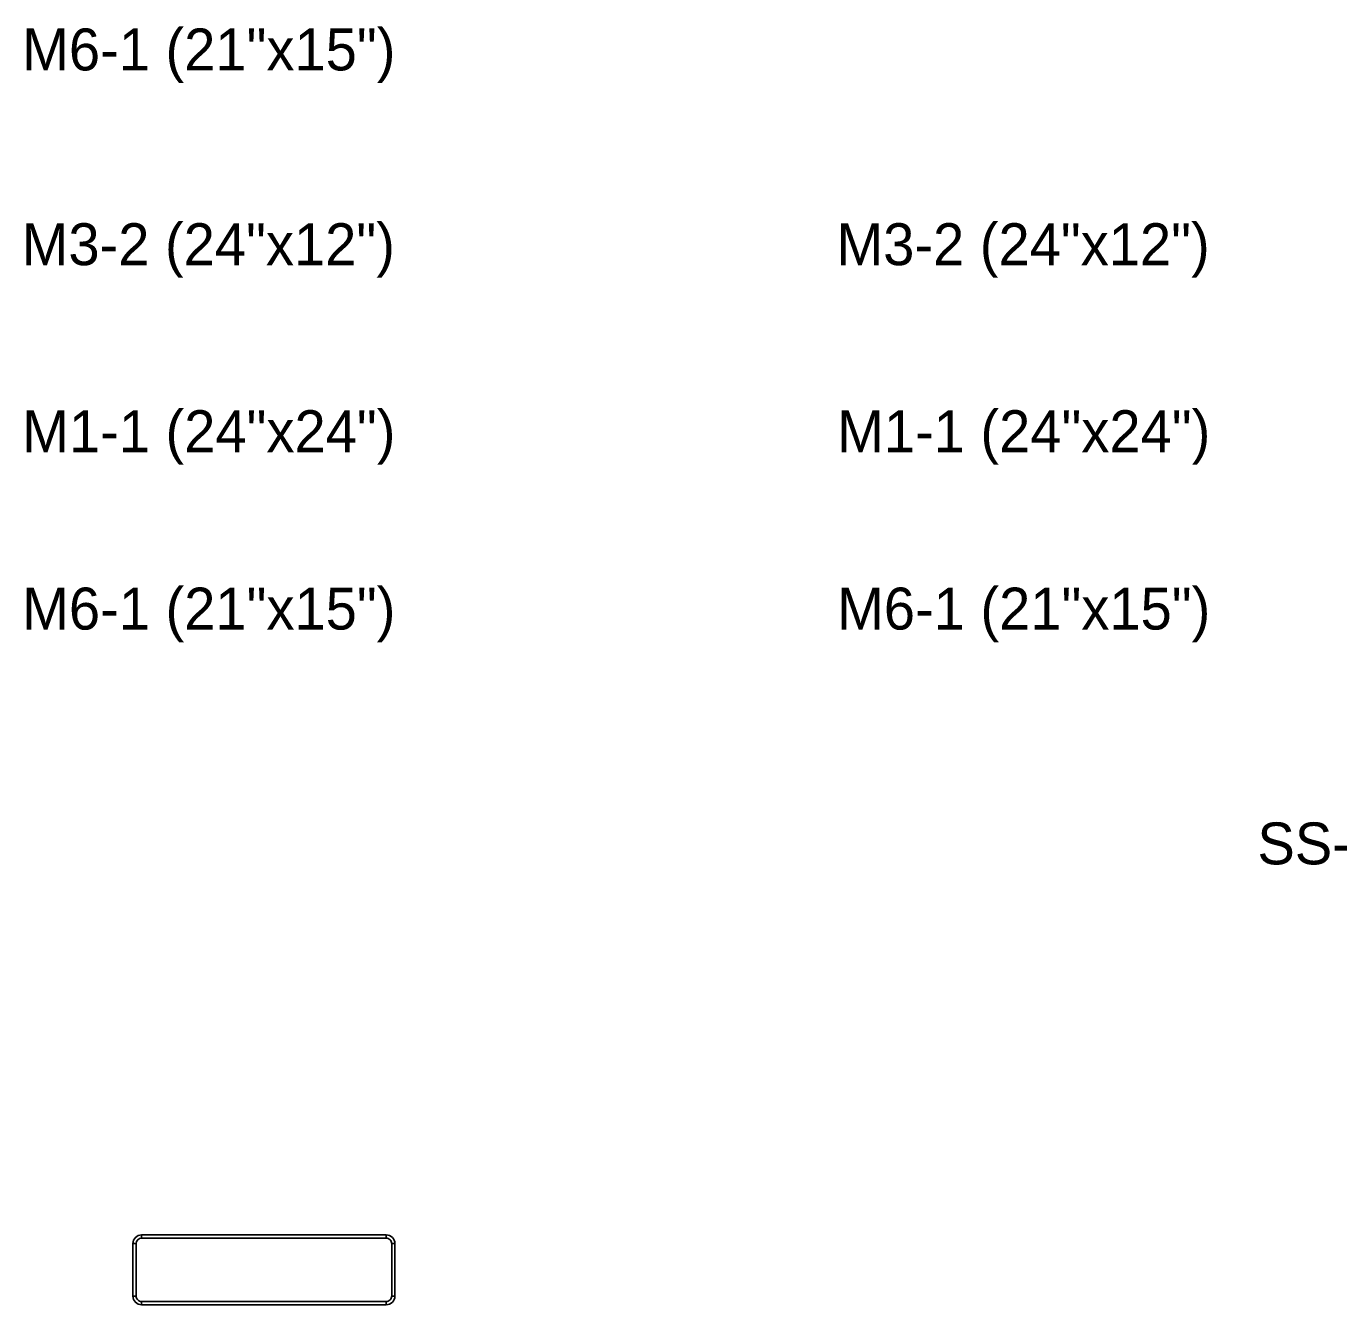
# Model space of a CAD drawing. Extents: x 620856.8 to 620948.6, y 415598.8 to 415658.2.
# Drawn here: x 620886.61 to 620899.13, y 415630.2 to 415642.4 of the extents above; entities that cross this region are included whole.
import ezdxf

# ---------------------------------------------------------------- set-up
doc = ezdxf.new("R2010")
doc.units = 0
doc.layers.add('SIGNS', color=7, linetype='Continuous')

msp = doc.modelspace()

# ---------------------------------------------------------------- linework, layer by layer
at = {"layer": 'SIGNS'}
for p, q in [((620887.707, 415630.835), (620887.707, 415630.866)), ((620890.041, 415630.866), (620890.041, 415630.835)), ((620887.624, 415630.782), (620887.655, 415630.782)), ((620890.093, 415630.782), (620890.124, 415630.782)), ((620887.655, 415630.282), (620887.624, 415630.282)), ((620887.707, 415630.199), (620887.707, 415630.23)), ((620890.041, 415630.23), (620890.041, 415630.199)), ((620890.124, 415630.282), (620890.093, 415630.282))]:
    msp.add_line(p, q, dxfattribs=at)
for points in [[(620890.041, 415630.835), (620887.707, 415630.835), (620887.707, 415630.866), (620890.041, 415630.866), (620890.041, 415630.835), (620890.041, 415630.835)], [(620887.655, 415630.782), (620887.655, 415630.282), (620887.624, 415630.282), (620887.624, 415630.782), (620887.655, 415630.782), (620887.655, 415630.782)], [(620890.093, 415630.282), (620890.093, 415630.782), (620890.124, 415630.782), (620890.124, 415630.282), (620890.093, 415630.282), (620890.093, 415630.282)], [(620887.707, 415630.23), (620890.041, 415630.23), (620890.041, 415630.199), (620887.707, 415630.199), (620887.707, 415630.23), (620887.707, 415630.23)]]:
    msp.add_lwpolyline(points, close=True, dxfattribs=at)
for centre, radius, start, end in [((620887.707, 415630.782), 0.0833, 90.0002, 179.9998), ((620887.707, 415630.782), 0.0521, 90.0002, 179.9998), ((620890.041, 415630.782), 0.0833, 360, 90.0002), ((620890.041, 415630.782), 0.0521, 360, 90.0002), ((620887.707, 415630.282), 0.0833, 179.9998, 270.0001), ((620887.707, 415630.282), 0.0521, 179.9998, 270.0001), ((620890.041, 415630.282), 0.0833, 270.0001, 0.0003), ((620890.041, 415630.282), 0.0521, 270.0001, 0.0003)]:
    msp.add_arc(centre, radius, start, end, dxfattribs=at)

# ---------------------------------------------------------------- texts
for s, p in [('M6-1 (21"x15")', (620886.568, 415641.974)), ('M3-2 (24"x12")', (620886.563, 415640.116)), ('M3-2 (24"x12")', (620894.337, 415640.116)), ('M1-1 (24"x24")', (620886.568, 415638.332)), ('M1-1 (24"x24")', (620894.343, 415638.332)), ('M6-1 (21"x15")', (620886.568, 415636.64)), ('M6-1 (21"x15")', (620894.343, 415636.64)), ('SS-HWY59-17-STA39+50SB', (620898.353, 415634.4))]:
    msp.add_text(s, height=0.4, rotation=0, dxfattribs=at).set_placement(p)

doc.saveas('drawing.dxf')
